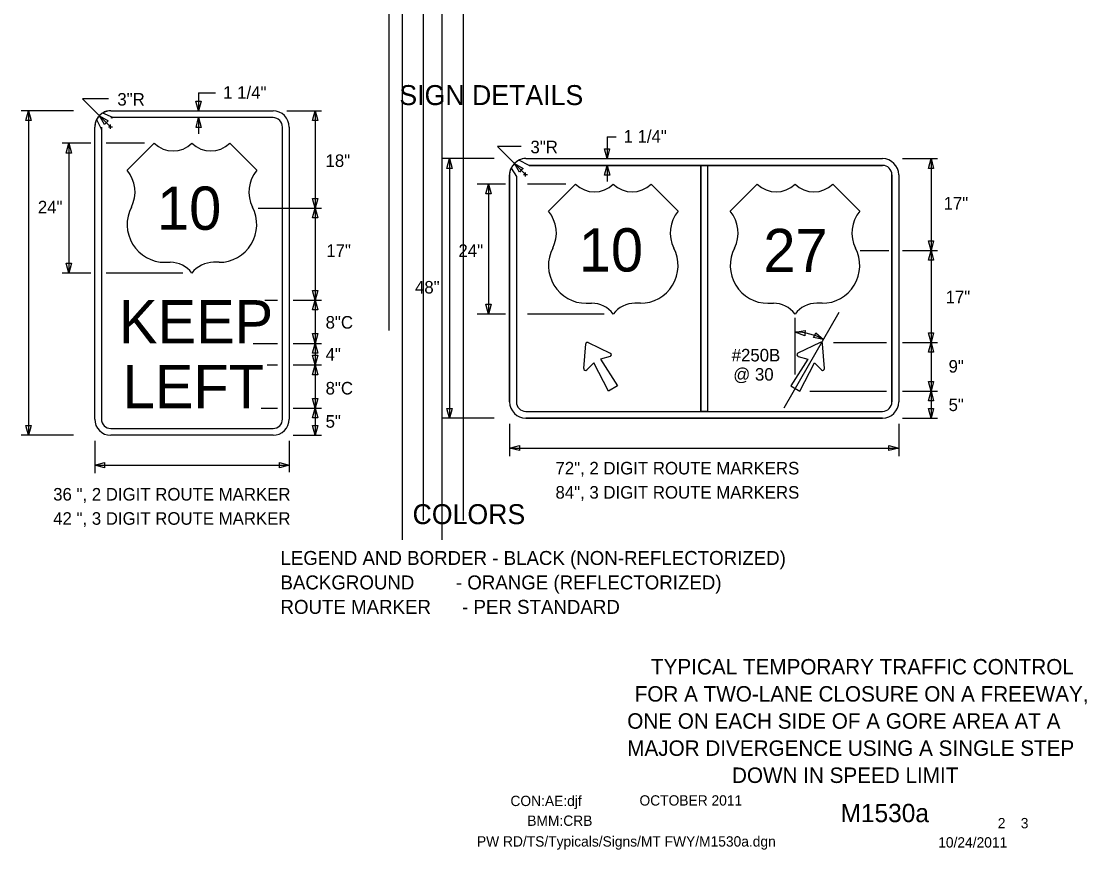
# Model space of a CAD drawing. Extents: x 16452 to 19508, y 5713 to 7079.
# Drawn here: x 17826 to 18466, y 5932 to 6430 of the extents above; entities that cross this region are included whole.
import ezdxf

# ---------------------------------------------------------------- set-up
doc = ezdxf.new("R2010")
doc.units = 0
for name, color, linetype in [('ALI_LEGAL_EX', 7, 'Continuous'), ('BORDER', 7, 'Continuous'), ('BORDER_SIGNAL_WO', 7, 'Continuous'), ('TRAFFIC_SIGNS_PR', 7, 'Continuous'), ('TYPICAL_EX', 7, 'Continuous'), ('TYPICAL_TEXT_DIMEN_PR', 7, 'Continuous')]:
    doc.layers.add(name, color=color, linetype=linetype)

msp = doc.modelspace()

# ---------------------------------------------------------------- linework, layer by layer
at = {"layer": 'ALI_LEGAL_EX'}
for p, q in [((18054.48, 7078.99), (18054.48, 6260.86)), ((18078.48, 7078.99), (18078.48, 6260.86)), ((18054.48, 6981.91), (18054.48, 6118)), ((18078.48, 6981.91), (18078.48, 6118)), ((18046.81, 6243.91), (18046.81, 6744.25)), ((18067.45, 6129.67), (18067.45, 6630.02)), ((18091.45, 6129.67), (18091.45, 6630.02))]:
    msp.add_line(p, q, dxfattribs=at)
at = {"layer": 'TRAFFIC_SIGNS_PR'}
for p, q in [((17879.4, 6375.92), (17976.9, 6375.92)), ((17871.82, 6372.3), (17870.82, 6370.79)), ((17870.84, 6370.72), (17873.72, 6364.68)), ((17880.61, 6371.86), (17874.51, 6374.6)), ((17976.9, 6371.86), (17879.4, 6371.86)), ((17869.65, 6190.67), (17869.65, 6366.17)), ((17873.72, 6366.17), (17873.72, 6190.67)), ((17982.59, 6190.67), (17982.59, 6366.17)), ((17986.65, 6366.17), (17986.65, 6190.67)), ((18130.88, 6343.17), (18124.65, 6346.19)), ((18128.92, 6347.22), (18343.42, 6347.22)), ((18128.92, 6347.22), (18343.42, 6347.22)), ((18130.86, 6343.16), (18234.14, 6343.16)), ((18343.42, 6343.16), (18130.86, 6343.16)), ((18234.14, 6343.16), (18234.14, 6195.28)), ((18238.21, 6343.16), (18238.21, 6195.28)), ((18238.21, 6343.16), (18343.42, 6343.16)), ((18119.17, 6337.47), (18119.17, 6200.97)), ((18119.17, 6200.97), (18119.17, 6337.47)), ((18120.09, 6341.48), (18123.23, 6336.44)), ((18349.11, 6337.47), (18349.11, 6291.72)), ((18349.11, 6200.97), (18349.11, 6337.47)), ((18353.17, 6337.47), (18353.17, 6200.97)), ((18353.17, 6337.47), (18353.17, 6200.97)), ((18123.24, 6336.42), (18123.24, 6200.97)), ((18123.24, 6336.42), (18123.24, 6200.97)), ((18349.11, 6291.72), (18349.11, 6200.97)), ((18163.78, 6221.08), (18164.93, 6235.8)), ((18166.44, 6236.67), (18179.75, 6230.31)), ((18305.91, 6236.67), (18292.59, 6230.31)), ((18308.57, 6221.08), (18307.42, 6235.8)), ((18128.92, 6195.28), (18343.42, 6195.28)), ((18128.92, 6191.22), (18343.42, 6191.22)), ((18343.42, 6191.22), (18128.92, 6191.22)), ((17879.4, 6184.98), (17976.9, 6184.98)), ((17976.9, 6180.92), (17879.4, 6180.92))]:
    msp.add_line(p, q, dxfattribs=at)
for points in [[(18130.86, 6343.16), (18130.85, 6343.16)], [(18123.23, 6336.44), (18123.24, 6336.42)], [(18179.59, 6228.34), (18173.87, 6226.76), (18184.09, 6210.59), (18178.69, 6207.47), (18169.79, 6224.41), (18165.57, 6220.24)], [(18292.76, 6228.34), (18298.48, 6226.76), (18288.26, 6210.59), (18293.66, 6207.47), (18302.56, 6224.41), (18306.78, 6220.24)]]:
    msp.add_lwpolyline(points, dxfattribs=at)
msp.add_lwpolyline([(18234.14, 6343.16), (18238.21, 6343.16), (18238.21, 6195.28), (18234.14, 6195.28)], close=True, dxfattribs=at)
for centre, radius, start, end in [((17879.4, 6366.17), 9.75, 90, 180), ((17878.82, 6368.34), 7.6, 85.58319, 124.53531), ((17976.9, 6366.17), 9.75, 0, 90), ((17876.69, 6366.76), 7.06, 145.86811, 184.82317), ((17880.01, 6376.28), 4.47, 262.2432, 277.7568), ((17976.9, 6366.17), 5.69, 0, 90), ((17868.26, 6365.43), 5.51, 352.24294, 7.75653), ((18128.92, 6337.47), 9.75, 90, 180), ((18128.92, 6337.47), 9.75, 90, 180), ((18128.25, 6340.65), 6.6, 84.11162, 123.06374), ((18129.86, 6350.34), 7.24, 277.81035, 278.05403), ((18343.42, 6337.47), 9.75, 0, 90), ((18343.42, 6337.47), 9.75, 0, 90), ((18343.42, 6337.47), 5.69, 0, 89.99421), ((18343.42, 6337.47), 5.69, 0, 90), ((18125.3, 6338.18), 6.17, 147.60925, 186.56283), ((18165.98, 6235.71), 1.06, 64.48226, 175.51774), ((18306.37, 6235.71), 1.06, 4.48226, 115.51774), ((18179.3, 6229.35), 1.06, 285.9885, 64.48226), ((18293.05, 6229.35), 1.06, 115.51774, 254.0115), ((18164.83, 6221), 1.06, 175.51775, 314.01151), ((18307.52, 6221), 1.06, 225.98849, 4.48225), ((18128.92, 6200.97), 9.75, 180, 270), ((18128.92, 6200.97), 9.75, 180, 270), ((18128.92, 6200.97), 5.69, 180, 270), ((18128.92, 6200.97), 5.69, 180, 270), ((18343.42, 6200.97), 9.75, 270, 0), ((18343.42, 6200.97), 5.69, 270, 0), ((18343.42, 6200.97), 9.75, 270, 0), ((18343.42, 6200.97), 5.69, 270, 0), ((17879.4, 6190.67), 9.75, 180, 270), ((17879.4, 6190.67), 5.69, 180, 270), ((17976.9, 6190.67), 5.69, 270, 0), ((17976.9, 6190.67), 9.75, 270, 0)]:
    msp.add_arc(centre, radius, start, end, dxfattribs=at)
at = {"layer": 'TYPICAL_EX'}
for p, q in [((17889.15, 6340.17), (17905.4, 6356.42)), ((17967.16, 6340.17), (17950.9, 6356.42)), ((18142.53, 6315.56), (18158.78, 6331.81)), ((18220.54, 6315.56), (18204.28, 6331.81)), ((18251.81, 6315.56), (18268.06, 6331.81)), ((18329.82, 6315.56), (18313.56, 6331.81)), ((17911.88, 6284.88), (17915.13, 6284.88)), ((17944.42, 6284.88), (17941.17, 6284.88)), ((18165.26, 6260.27), (18168.51, 6260.27)), ((18197.81, 6260.27), (18194.56, 6260.27)), ((18274.54, 6260.27), (18277.79, 6260.27)), ((18307.09, 6260.27), (18303.84, 6260.27))]:
    msp.add_line(p, q, dxfattribs=at)
for centre, radius, start, end in [((17916.78, 6368.26), 16.42, 226.14041, 313.85958), ((17939.53, 6368.26), 16.42, 226.14042, 313.85959), ((17873.75, 6327.16), 20.16, 333.09768, 40.19361), ((17982.55, 6327.16), 20.16, 139.80639, 206.90233), ((18170.16, 6343.65), 16.42, 226.14041, 313.85958), ((18192.91, 6343.65), 16.42, 226.14042, 313.85959), ((18279.44, 6343.65), 16.42, 226.14041, 313.85958), ((18302.19, 6343.65), 16.42, 226.14042, 313.85959), ((17911.92, 6307.6), 22.73, 152.6698, 269.90132), ((17944.38, 6307.6), 22.73, 270.09868, 27.3302), ((18127.13, 6302.55), 20.16, 333.09768, 40.19361), ((18235.94, 6302.55), 20.16, 139.80639, 206.90233), ((18236.41, 6302.55), 20.16, 333.09768, 40.19361), ((18345.21, 6302.55), 20.16, 139.80639, 206.90233), ((18165.3, 6282.99), 22.73, 152.6698, 269.90132), ((18197.77, 6282.99), 22.73, 270.09868, 27.3302), ((18274.58, 6282.99), 22.73, 152.6698, 269.90132), ((18307.05, 6282.99), 22.73, 270.09868, 27.3302), ((17915.17, 6268.6), 16.28, 37.1038, 90.13853), ((17941.13, 6268.6), 16.28, 89.86147, 142.8962), ((18168.55, 6243.99), 16.28, 37.1038, 90.13853), ((18194.52, 6243.99), 16.28, 89.86147, 142.8962), ((18277.83, 6243.99), 16.28, 37.1038, 90.13853), ((18303.8, 6243.99), 16.28, 89.86147, 142.8962)]:
    msp.add_arc(centre, radius, start, end, dxfattribs=at)
at = {"layer": 'TYPICAL_TEXT_DIMEN_PR'}
for p, q in [((17878.02, 6383.2), (17862.37, 6383.2)), ((17862.37, 6383.2), (17872.6, 6372.97)), ((17932.12, 6375.92), (17930.55, 6381.78)), ((17930.55, 6381.78), (17932.12, 6381.78)), ((17932.12, 6386.68), (17932.12, 6375.92)), ((17932.12, 6386.68), (17942.23, 6386.68)), ((17932.12, 6381.78), (17933.69, 6381.78)), ((17933.69, 6381.78), (17932.12, 6375.92)), ((17856.82, 6375.92), (17825.53, 6375.92)), ((17828.3, 6370.06), (17829.87, 6375.92)), ((17829.87, 6375.92), (17829.87, 6180.92)), ((17829.87, 6375.92), (17831.44, 6370.06)), ((17985.19, 6375.92), (18006.15, 6375.92)), ((18000.69, 6370.06), (18002.26, 6375.92)), ((18002.26, 6375.92), (18002.26, 6317.42)), ((18002.26, 6375.92), (18003.83, 6370.06)), ((17829.87, 6370.06), (17828.3, 6370.06)), ((17831.44, 6370.06), (17829.87, 6370.06)), ((17872.6, 6372.97), (17879.16, 6366.41)), ((17875.64, 6367.71), (17872.6, 6372.97)), ((17872.6, 6372.97), (17877.86, 6369.93)), ((17876.75, 6368.82), (17875.64, 6367.71)), ((17877.86, 6369.93), (17876.75, 6368.82)), ((17930.6, 6365.99), (17932.17, 6371.86)), ((17932.17, 6371.86), (17932.17, 6362.11)), ((17932.17, 6371.86), (17933.74, 6365.99)), ((18002.26, 6370.06), (18000.69, 6370.06)), ((18003.83, 6370.06), (18002.26, 6370.06)), ((17877.95, 6366.41), (17880.37, 6366.41)), ((17879.16, 6365.2), (17879.16, 6367.62)), ((17932.17, 6365.99), (17930.6, 6365.99)), ((17933.74, 6365.99), (17932.17, 6365.99)), ((17867.28, 6356.42), (17850.15, 6356.42)), ((17852.48, 6350.56), (17854.05, 6356.42)), ((17854.05, 6356.42), (17854.05, 6278.42)), ((17854.05, 6356.42), (17855.62, 6350.56)), ((17899.52, 6356.42), (17876.64, 6356.42)), ((18177.78, 6360.37), (18177.78, 6347.22)), ((18177.78, 6360.37), (18183.31, 6360.37)), ((17854.05, 6350.56), (17852.48, 6350.56)), ((17855.62, 6350.56), (17854.05, 6350.56)), ((18126.06, 6354.5), (18111.89, 6354.5)), ((18111.89, 6354.5), (18122.04, 6344.36)), ((18177.78, 6347.22), (18176.21, 6353.08)), ((18176.21, 6353.08), (18177.78, 6353.08)), ((18177.78, 6353.08), (18179.35, 6353.08)), ((18179.35, 6353.08), (18177.78, 6347.22)), ((18109.94, 6347.22), (18078.65, 6347.22)), ((18081.42, 6341.36), (18082.99, 6347.22)), ((18082.99, 6347.22), (18082.99, 6191.22)), ((18082.99, 6347.22), (18084.56, 6341.36)), ((18122.04, 6344.36), (18128.68, 6337.71)), ((18125.07, 6339.1), (18122.04, 6344.36)), ((18122.04, 6344.36), (18127.29, 6341.32)), ((18176.26, 6337.3), (18177.83, 6343.16)), ((18176.26, 6337.3), (18177.83, 6343.16)), ((18177.83, 6343.16), (18177.83, 6333.41)), ((18177.83, 6343.16), (18179.4, 6337.3)), ((18177.83, 6343.16), (18179.4, 6337.3)), ((18355.55, 6347.22), (18376.51, 6347.22)), ((18371.04, 6341.36), (18372.61, 6347.22)), ((18372.61, 6347.22), (18372.61, 6291.97)), ((18372.61, 6347.22), (18374.18, 6341.36)), ((18082.99, 6341.36), (18081.42, 6341.36)), ((18084.56, 6341.36), (18082.99, 6341.36)), ((18126.18, 6340.21), (18125.07, 6339.1)), ((18127.29, 6341.32), (18126.18, 6340.21)), ((18127.48, 6337.71), (18129.89, 6337.71)), ((18128.68, 6336.5), (18128.68, 6338.92)), ((18177.83, 6337.3), (18176.26, 6337.3)), ((18177.83, 6337.3), (18176.26, 6337.3)), ((18179.4, 6337.3), (18177.83, 6337.3)), ((18179.4, 6337.3), (18177.83, 6337.3)), ((18372.61, 6341.36), (18371.04, 6341.36)), ((18374.18, 6341.36), (18372.61, 6341.36)), ((18116.8, 6331.81), (18099.67, 6331.81)), ((18104.97, 6325.95), (18106.54, 6331.81)), ((18106.54, 6331.81), (18106.54, 6253.81)), ((18106.54, 6331.81), (18108.11, 6325.95)), ((18152.9, 6331.81), (18130.03, 6331.81)), ((18106.54, 6325.95), (18104.97, 6325.95)), ((18108.11, 6325.95), (18106.54, 6325.95)), ((17968.04, 6317.42), (18006.15, 6317.42)), ((18002.26, 6317.42), (18000.69, 6323.28)), ((18000.69, 6323.28), (18002.26, 6323.28)), ((18000.69, 6311.56), (18002.26, 6317.42)), ((18002.26, 6323.28), (18003.83, 6323.28)), ((18003.83, 6323.28), (18002.26, 6317.42)), ((18002.26, 6317.42), (18002.26, 6262.17)), ((18002.26, 6317.42), (18003.83, 6311.56)), ((18002.26, 6311.56), (18000.69, 6311.56)), ((18003.83, 6311.56), (18002.26, 6311.56)), ((18329.99, 6291.97), (18347.14, 6291.97)), ((18355.55, 6291.97), (18376.51, 6291.97)), ((18372.61, 6291.97), (18371.04, 6297.83)), ((18371.04, 6297.83), (18372.61, 6297.83)), ((18371.04, 6286.11), (18372.61, 6291.97)), ((18372.61, 6297.83), (18374.18, 6297.83)), ((18374.18, 6297.83), (18372.61, 6291.97)), ((18372.61, 6291.97), (18372.61, 6236.72)), ((18372.61, 6291.97), (18374.18, 6286.11)), ((18372.61, 6286.11), (18371.04, 6286.11)), ((18374.18, 6286.11), (18372.61, 6286.11)), ((17854.05, 6278.42), (17852.48, 6284.28)), ((17852.48, 6284.28), (17854.05, 6284.28)), ((17854.05, 6284.28), (17855.62, 6284.28)), ((17855.62, 6284.28), (17854.05, 6278.42)), ((17867.28, 6278.42), (17850.15, 6278.42)), ((17922.64, 6278.42), (17876.64, 6278.42)), ((18002.26, 6262.17), (18000.69, 6268.03)), ((18000.69, 6268.03), (18002.26, 6268.03)), ((18002.26, 6268.03), (18003.83, 6268.03)), ((18003.83, 6268.03), (18002.26, 6262.17)), ((17971.98, 6262.17), (17979.66, 6262.17)), ((17989.03, 6262.17), (18006.15, 6262.17)), ((18000.69, 6256.31), (18002.26, 6262.17)), ((18002.26, 6262.17), (18002.26, 6236.17)), ((18002.26, 6262.17), (18003.83, 6256.31)), ((18106.54, 6253.81), (18104.97, 6259.67)), ((18104.97, 6259.67), (18106.54, 6259.67)), ((18106.54, 6259.67), (18108.11, 6259.67)), ((18108.11, 6259.67), (18106.54, 6253.81)), ((18002.26, 6256.31), (18000.69, 6256.31)), ((18003.83, 6256.31), (18002.26, 6256.31)), ((18116.8, 6253.81), (18099.67, 6253.81)), ((18176.03, 6253.81), (18130.03, 6253.81)), ((18284.21, 6197.32), (18317.45, 6254.91)), ((18290.96, 6217.48), (18290.96, 6251.47)), ((18002.26, 6236.17), (18000.69, 6242.03)), ((18000.69, 6242.03), (18002.26, 6242.03)), ((18002.26, 6242.03), (18003.83, 6242.03)), ((18003.83, 6242.03), (18002.26, 6236.17)), ((18290.99, 6242.91), (18296.98, 6243.87)), ((18296.66, 6240.75), (18290.99, 6242.91)), ((18296.82, 6242.31), (18296.66, 6240.75)), ((18296.98, 6243.87), (18296.82, 6242.31)), ((18301.98, 6239.59), (18302.66, 6241.01)), ((18302.66, 6241.01), (18303.34, 6242.42)), ((18303.34, 6242.42), (18307.94, 6238.46)), ((18372.61, 6236.72), (18371.04, 6242.58)), ((18371.04, 6242.58), (18372.61, 6242.58)), ((18372.61, 6242.58), (18374.18, 6242.58)), ((18374.18, 6242.58), (18372.61, 6236.72)), ((17964.96, 6236.17), (17979.66, 6236.17)), ((17989.03, 6236.17), (18006.15, 6236.17)), ((18000.69, 6230.31), (18002.26, 6236.17)), ((18002.26, 6236.17), (18002.26, 6223.17)), ((18002.26, 6236.17), (18003.83, 6230.31)), ((18307.94, 6238.46), (18301.98, 6239.59)), ((18313.91, 6236.72), (18345.78, 6236.72)), ((18355.55, 6236.72), (18376.51, 6236.72)), ((18371.04, 6230.86), (18372.61, 6236.72)), ((18372.61, 6236.72), (18372.61, 6207.47)), ((18372.61, 6236.72), (18374.18, 6230.86)), ((18002.26, 6230.31), (18000.69, 6230.31)), ((18002.26, 6223.17), (18000.69, 6229.03)), ((18000.69, 6229.03), (18002.26, 6229.03)), ((18003.83, 6230.31), (18002.26, 6230.31)), ((18002.26, 6229.03), (18003.83, 6229.03)), ((18003.83, 6229.03), (18002.26, 6223.17)), ((18372.61, 6230.86), (18371.04, 6230.86)), ((18374.18, 6230.86), (18372.61, 6230.86)), ((17973.32, 6223.17), (17979.66, 6223.17)), ((17989.03, 6223.17), (18006.15, 6223.17)), ((18000.69, 6217.31), (18002.26, 6223.17)), ((18002.26, 6223.17), (18002.26, 6197.17)), ((18002.26, 6223.17), (18003.83, 6217.31)), ((18002.26, 6217.31), (18000.69, 6217.31)), ((18003.83, 6217.31), (18002.26, 6217.31)), ((18372.61, 6207.47), (18371.04, 6213.33)), ((18371.04, 6213.33), (18372.61, 6213.33)), ((18372.61, 6213.33), (18374.18, 6213.33)), ((18374.18, 6213.33), (18372.61, 6207.47)), ((18002.26, 6197.17), (18000.69, 6203.03)), ((18000.69, 6203.03), (18002.26, 6203.03)), ((18002.26, 6203.03), (18003.83, 6203.03)), ((18003.83, 6203.03), (18002.26, 6197.17)), ((18299.78, 6207.47), (18345.78, 6207.47)), ((18355.55, 6207.47), (18376.51, 6207.47)), ((18371.04, 6201.61), (18372.61, 6207.47)), ((18372.61, 6207.47), (18372.61, 6191.22)), ((18372.61, 6207.47), (18374.18, 6201.61)), ((17969.82, 6197.17), (17979.66, 6197.17)), ((17989.03, 6197.17), (18006.15, 6197.17)), ((18000.69, 6191.31), (18002.26, 6197.17)), ((18002.26, 6197.17), (18002.26, 6180.92)), ((18002.26, 6197.17), (18003.83, 6191.31)), ((18082.99, 6191.22), (18081.42, 6197.08)), ((18081.42, 6197.08), (18082.99, 6197.08)), ((18082.99, 6197.08), (18084.56, 6197.08)), ((18084.56, 6197.08), (18082.99, 6191.22)), ((18372.61, 6201.61), (18371.04, 6201.61)), ((18372.61, 6191.22), (18371.04, 6197.08)), ((18371.04, 6197.08), (18372.61, 6197.08)), ((18374.18, 6201.61), (18372.61, 6201.61)), ((18372.61, 6197.08), (18374.18, 6197.08)), ((18374.18, 6197.08), (18372.61, 6191.22)), ((18002.26, 6191.31), (18000.69, 6191.31)), ((18003.83, 6191.31), (18002.26, 6191.31)), ((18109.94, 6191.22), (18078.65, 6191.22)), ((18355.55, 6191.22), (18372.67, 6191.22)), ((18355.55, 6191.22), (18376.51, 6191.22)), ((18355.55, 6191.22), (18372.67, 6191.22)), ((17829.87, 6180.92), (17828.3, 6186.78)), ((17828.3, 6186.78), (17829.87, 6186.78)), ((17829.87, 6186.78), (17831.44, 6186.78)), ((17831.44, 6186.78), (17829.87, 6180.92)), ((18002.26, 6180.92), (18000.69, 6186.78)), ((18000.69, 6186.78), (18002.26, 6186.78)), ((18002.26, 6186.78), (18003.83, 6186.78)), ((18003.83, 6186.78), (18002.26, 6180.92)), ((18119.17, 6187.88), (18119.17, 6168.31)), ((18353.17, 6187.88), (18353.17, 6168.31)), ((17856.82, 6180.92), (17825.53, 6180.92)), ((17869.65, 6177.57), (17869.65, 6158.22)), ((17986.65, 6177.57), (17986.65, 6158.68)), ((17989.03, 6180.92), (18006.15, 6180.92)), ((18119.17, 6173.25), (18125.04, 6174.82)), ((18119.17, 6173.25), (18353.17, 6173.25)), ((18125.04, 6171.68), (18119.17, 6173.25)), ((18125.04, 6174.82), (18125.04, 6173.25)), ((18125.04, 6173.25), (18125.04, 6171.68)), ((18347.31, 6173.25), (18347.31, 6174.82)), ((18347.31, 6174.82), (18353.17, 6173.25)), ((18353.17, 6173.25), (18347.31, 6171.68)), ((18347.31, 6171.68), (18347.31, 6173.25)), ((17869.65, 6162.95), (17875.51, 6164.52)), ((17875.51, 6164.52), (17875.51, 6162.95)), ((17980.79, 6162.95), (17980.79, 6164.52)), ((17980.79, 6164.52), (17986.65, 6162.95)), ((17869.65, 6162.95), (17986.65, 6162.95)), ((17875.51, 6161.38), (17869.65, 6162.95)), ((17875.51, 6162.95), (17875.51, 6161.38)), ((17986.65, 6162.95), (17980.79, 6161.38)), ((17980.79, 6161.38), (17980.79, 6162.95))]:
    msp.add_line(p, q, dxfattribs=at)
msp.add_arc((18291.16, 6208.48), 34.39, 60.74521, 90.32117, dxfattribs=at)

# ---------------------------------------------------------------- texts
at = {"layer": 'BORDER'}
for s, p in [('TYPICAL TEMPORARY TRAFFIC CONTROL', (18204.21, 6037.14)), ('FOR A TWO-LANE CLOSURE ON A FREEWAY,', (18194.41, 6020.84)), ('ONE ON EACH SIDE OF A GORE AREA AT A ', (18189.92, 6004.54)), ('MAJOR DIVERGENCE USING A SINGLE STEP ', (18189.92, 5988.24)), ('DOWN IN SPEED LIMIT', (18252.92, 5971.94))]:
    msp.add_text(s, height=9.3, dxfattribs=at).set_placement(p)
at = {"layer": 'BORDER_SIGNAL_WO'}
for s, height, p in [('CON:AE:djf  ', 6.2, (18119.69, 5958.06)), ('    OCTOBER 2011    ', 6.2, (18188.08, 5958.34)), ('    M1530a   ', 11, (18301.86, 5948.38)), ('BMM:CRB   ', 6.2, (18129.81, 5946.17)), (' 2    3 ', 6.2, (18410.45, 5944.7)), ('PW RD/TS/Typicals/Signs/MT FWY/M1530a.dgn      ', 6.2, (18099.55, 5933.71)), ('10/24/2011    ', 6.2, (18376.93, 5933.13))]:
    msp.add_text(s, height=height, dxfattribs=at).set_placement(p)
at = {"layer": 'TRAFFIC_SIGNS_PR'}
for s, p in [('10', (17907.12, 6304.42)), ('10', (18160.77, 6279.35)), ('27', (18271.78, 6278.99)), ('KEEP', (17884.26, 6236.17)), ('LEFT', (17886.49, 6197.17))]:
    msp.add_text(s, height=26, dxfattribs=at).set_placement(p)
at = {"layer": 'TYPICAL_TEXT_DIMEN_PR'}
for s, height, p in [('1 1/4"', 7.55, (17946.93, 6383.17)), ('SIGN DETAILS', 12, (18052.88, 6379.39)), ('3"R', 7.55, (17883.29, 6379.08)), ('1 1/4"', 7.55, (18187.71, 6356.8)), ('3"R', 7.55, (18131.71, 6350.43)), ('18"', 7.55, (18008.49, 6342.19)), ('17"', 7.55, (18380.18, 6316.58)), ('24"', 7.55, (17835.5, 6314.3)), ('17"', 7.55, (18008.95, 6288.14)), ('24"', 7.55, (18088.4, 6288.14)), ('48"', 7.55, (18062.29, 6266.12)), ('17"', 7.55, (18381.39, 6260.22)), ('8"C', 7.55, (18008.53, 6245.03)), ('4" ', 7.55, (18008.53, 6225.77)), ('#250B', 7.55, (18252.73, 6225.31)), ('@ 30', 7.55, (18253.68, 6213.76)), ('9"', 7.55, (18383.17, 6218.57)), ('8"C', 7.55, (18008.53, 6205.44)), ('5"', 7.55, (18383.16, 6195.47)), ('5" ', 7.55, (18008.53, 6185.46)), ('72", 2 DIGIT ROUTE MARKERS', 7.55, (18146.75, 6157.39)), ('36 ", 2 DIGIT ROUTE MARKER', 7.55, (17844.7, 6141.69)), ('84", 3 DIGIT ROUTE MARKERS', 7.55, (18146.75, 6142.84)), ('COLORS', 12, (18060.82, 6127.5)), ('42 ", 3 DIGIT ROUTE MARKER', 7.55, (17844.7, 6127.14)), ('LEGEND AND BORDER - BLACK (NON-REFLECTORIZED)', 8.4, (17981.39, 6102.97)), ('BACKGROUND        - ORANGE (REFLECTORIZED)', 8.4, (17981.39, 6088.27)), ('ROUTE MARKER      - PER STANDARD', 8.4, (17981.39, 6073.57))]:
    msp.add_text(s, height=height, dxfattribs=at).set_placement(p)

doc.saveas('drawing.dxf')
